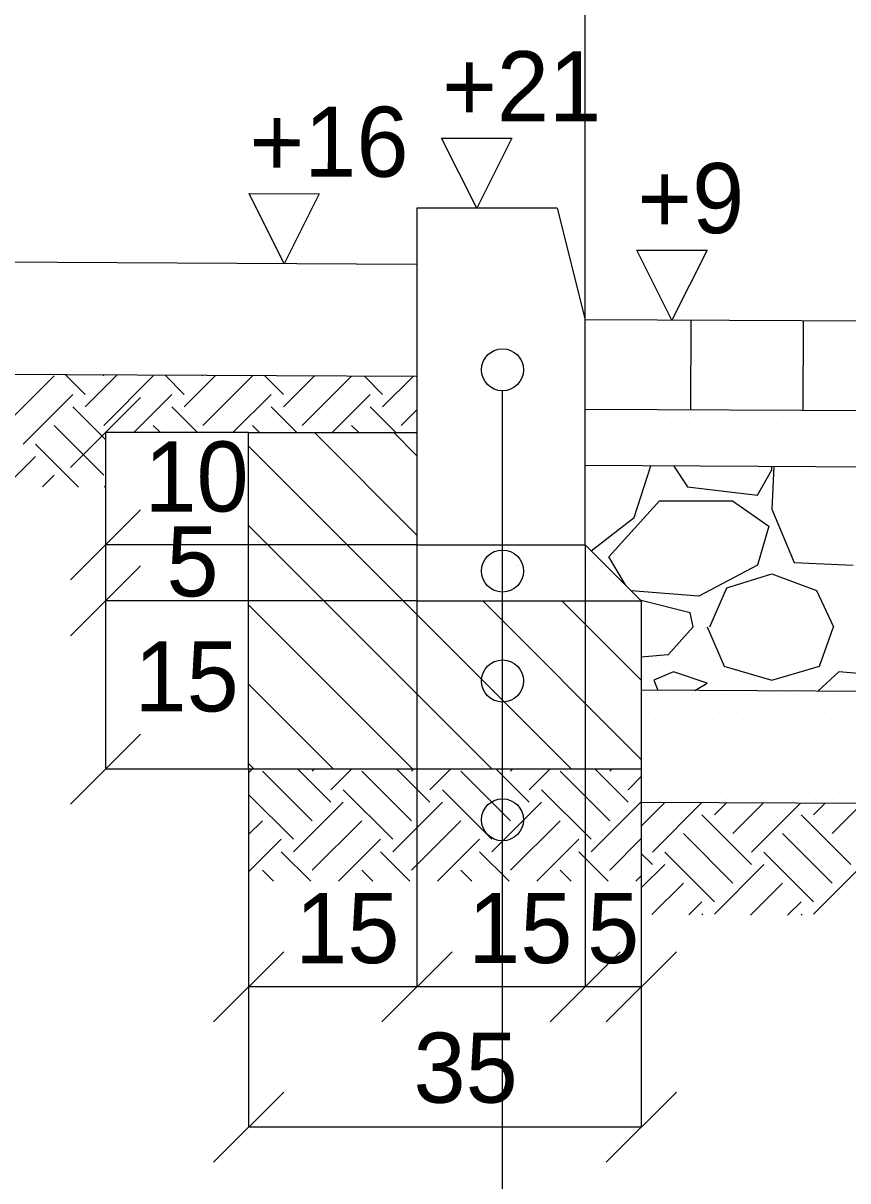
# Model space of a CAD drawing. Extents: x -219625893 to 7498339, y 5791790 to 5792761.
# Drawn here: x 7495188.44 to 7495203.14, y 5791857.84 to 5791878.48 of the extents above; entities that cross this region are included whole.
import ezdxf

# ---------------------------------------------------------------- set-up
doc = ezdxf.new("R2010")
doc.units = 0
for name, color, linetype in [('D_kons_wyp_grunt', 7, 'Continuous'), ('D_kons_wyp_kruszywo_lamane', 7, 'Continuous'), ('D_kons_wyp_podsypka_cem-piask', 7, 'Continuous'), ('D_kons_wyp_pospolka', 7, 'Continuous'), ('D_robocze_1', 7, 'Continuous'), ('D_wymiary_500', 7, 'Continuous'), ('Level 1', 7, 'Continuous'), ('Level 10', 7, 'Continuous'), ('Level 8', 7, 'Continuous'), ('wymiary', 7, 'Continuous')]:
    doc.layers.add(name, color=color, linetype=linetype)

msp = doc.modelspace()

# ---------------------------------------------------------------- linework, layer by layer
at = {"layer": 'D_kons_wyp_grunt'}
for p, q in [((7495188.107, 5791871.309), (7495188.991, 5791872.193)), ((7495189.543, 5791871.862), (7495189.191, 5791872.213)), ((7495189.543, 5791871.641), (7495190.111, 5791872.209)), ((7495189.875, 5791872.193), (7495189.858, 5791872.21)), ((7495189.875, 5791871.309), (7495190.758, 5791872.193)), ((7495191.311, 5791871.862), (7495190.968, 5791872.204)), ((7495191.311, 5791871.641), (7495191.87, 5791872.2)), ((7495191.642, 5791872.193), (7495191.634, 5791872.201)), ((7495191.642, 5791871.309), (7495192.526, 5791872.193)), ((7495193.079, 5791871.862), (7495192.745, 5791872.196)), ((7495193.079, 5791871.641), (7495193.629, 5791872.191)), ((7495193.41, 5791871.309), (7495194.289, 5791872.188)), ((7495194.846, 5791871.862), (7495194.521, 5791872.187)), ((7495194.846, 5791871.641), (7495195.388, 5791872.182)), ((7495188.438, 5791870.978), (7495189.322, 5791871.862)), ((7495190.41, 5791871.182), (7495191.09, 5791871.862)), ((7495192.178, 5791871.182), (7495192.858, 5791871.862)), ((7495193.946, 5791871.182), (7495194.625, 5791871.862)), ((7495189.906, 5791871.057), (7495189.322, 5791871.641)), ((7495191.549, 5791871.182), (7495191.09, 5791871.641)), ((7495193.316, 5791871.182), (7495192.858, 5791871.641)), ((7495195.084, 5791871.182), (7495194.625, 5791871.641)), ((7495195.178, 5791871.309), (7495195.458, 5791871.59)), ((7495189.875, 5791870.425), (7495188.991, 5791871.309)), ((7495190.886, 5791871.182), (7495190.758, 5791871.309)), ((7495192.653, 5791871.182), (7495192.526, 5791871.309)), ((7495194.421, 5791871.182), (7495194.294, 5791871.309)), ((7495189.425, 5791870.212), (7495188.659, 5791870.978)), ((7495188.121, 5791870.219), (7495188.659, 5791870.757)), ((7495188.781, 5791870.215), (7495188.991, 5791870.425)), ((7495189.88, 5791870.21), (7495189.906, 5791870.235)), ((7495192.458, 5791865.118), (7495192.523, 5791865.182)), ((7495193.922, 5791864.593), (7495193.333, 5791865.182)), ((7495193.591, 5791865.145), (7495193.627, 5791865.182)), ((7495193.922, 5791864.814), (7495194.29, 5791865.182)), ((7495195.69, 5791864.593), (7495195.101, 5791865.182)), ((7495195.359, 5791865.145), (7495195.395, 5791865.182)), ((7495195.69, 5791864.814), (7495196.058, 5791865.182)), ((7495197.458, 5791864.593), (7495196.869, 5791865.182)), ((7495197.126, 5791865.145), (7495197.163, 5791865.182)), ((7495197.458, 5791864.814), (7495197.826, 5791865.182)), ((7495199.226, 5791864.593), (7495198.637, 5791865.182)), ((7495198.894, 5791865.145), (7495198.931, 5791865.182)), ((7495193.591, 5791864.262), (7495192.707, 5791865.145)), ((7495195.359, 5791864.262), (7495194.475, 5791865.145)), ((7495197.126, 5791864.262), (7495196.242, 5791865.145)), ((7495198.894, 5791864.262), (7495198.01, 5791865.145)), ((7495199.226, 5791864.814), (7495199.458, 5791865.047)), ((7495195.027, 5791863.93), (7495194.143, 5791864.814)), ((7495196.795, 5791863.93), (7495195.911, 5791864.814)), ((7495198.563, 5791863.93), (7495197.679, 5791864.814)), ((7495193.259, 5791863.93), (7495192.458, 5791864.731)), ((7495193.259, 5791863.709), (7495194.143, 5791864.593)), ((7495195.027, 5791863.709), (7495195.911, 5791864.593)), ((7495196.795, 5791863.709), (7495197.679, 5791864.593)), ((7495198.563, 5791863.709), (7495199.447, 5791864.593)), ((7495199.458, 5791864.167), (7495199.878, 5791864.587)), ((7495199.655, 5791863.701), (7495200.538, 5791864.584)), ((7495200.76, 5791864.364), (7495200.978, 5791864.582)), ((7495201.092, 5791864.033), (7495201.637, 5791864.578)), ((7495201.423, 5791863.701), (7495202.297, 5791864.575)), ((7495202.528, 5791864.364), (7495202.737, 5791864.573)), ((7495202.859, 5791864.033), (7495203.396, 5791864.57)), ((7495201.423, 5791863.48), (7495200.539, 5791864.364)), ((7495203.191, 5791863.48), (7495202.307, 5791864.364)), ((7495192.458, 5791864.013), (7495192.707, 5791864.262)), ((7495193.591, 5791863.378), (7495194.475, 5791864.262)), ((7495195.359, 5791863.378), (7495196.242, 5791864.262)), ((7495197.126, 5791863.378), (7495198.01, 5791864.262)), ((7495192.458, 5791863.35), (7495193.038, 5791863.93)), ((7495194.058, 5791863.182), (7495194.806, 5791863.93)), ((7495195.826, 5791863.182), (7495196.574, 5791863.93)), ((7495197.594, 5791863.182), (7495198.342, 5791863.93)), ((7495198.894, 5791863.378), (7495199.458, 5791863.942)), ((7495201.092, 5791863.149), (7495200.208, 5791864.033)), ((7495202.859, 5791863.149), (7495201.976, 5791864.033)), ((7495193.566, 5791863.182), (7495193.038, 5791863.709)), ((7495195.333, 5791863.182), (7495194.806, 5791863.709)), ((7495197.101, 5791863.182), (7495196.574, 5791863.709)), ((7495198.869, 5791863.182), (7495198.342, 5791863.709)), ((7495199.655, 5791863.48), (7495199.458, 5791863.678)), ((7495200.76, 5791862.817), (7495199.876, 5791863.701)), ((7495202.528, 5791862.817), (7495201.644, 5791863.701)), ((7495192.903, 5791863.182), (7495192.707, 5791863.378)), ((7495194.67, 5791863.182), (7495194.475, 5791863.378)), ((7495196.438, 5791863.182), (7495196.242, 5791863.378)), ((7495198.206, 5791863.182), (7495198.01, 5791863.378)), ((7495199.458, 5791863.062), (7495199.876, 5791863.48)), ((7495200.76, 5791862.596), (7495201.644, 5791863.48)), ((7495202.528, 5791862.596), (7495203.412, 5791863.48)), ((7495199.361, 5791863.182), (7495199.458, 5791863.279)), ((7495199.647, 5791862.588), (7495200.208, 5791863.149)), ((7495201.406, 5791862.58), (7495201.976, 5791863.149)), ((7495200.307, 5791862.585), (7495200.539, 5791862.817)), ((7495202.066, 5791862.576), (7495202.307, 5791862.817)), ((7495200.552, 5791862.584), (7495200.539, 5791862.596)), ((7495202.328, 5791862.575), (7495202.307, 5791862.596))]:
    msp.add_line(p, q, dxfattribs=at)
at = {"layer": 'D_kons_wyp_kruszywo_lamane'}
msp.add_line((7495198.582, 5791869.072), (7495198.567, 5791869.074), dxfattribs=at)
at = {"layer": 'D_kons_wyp_podsypka_cem-piask'}
for p, q in [((7495198.74, 5791871.343), (7495198.74, 5791871.343)), ((7495199.052, 5791871.343), (7495199.052, 5791871.343)), ((7495199.365, 5791871.343), (7495199.365, 5791871.343)), ((7495199.677, 5791871.343), (7495199.677, 5791871.343)), ((7495199.99, 5791871.343), (7495199.99, 5791871.343)), ((7495200.302, 5791871.343), (7495200.302, 5791871.343)), ((7495200.615, 5791871.343), (7495200.615, 5791871.343)), ((7495200.927, 5791871.343), (7495200.927, 5791871.343)), ((7495201.24, 5791871.343), (7495201.24, 5791871.343)), ((7495201.552, 5791871.343), (7495201.552, 5791871.343)), ((7495201.865, 5791871.343), (7495201.865, 5791871.343)), ((7495202.177, 5791871.343), (7495202.177, 5791871.343)), ((7495202.49, 5791871.343), (7495202.49, 5791871.343)), ((7495202.802, 5791871.343), (7495202.802, 5791871.343)), ((7495203.115, 5791871.343), (7495203.115, 5791871.343)), ((7495198.583, 5791871.031), (7495198.583, 5791871.031)), ((7495198.896, 5791871.031), (7495198.896, 5791871.031)), ((7495199.208, 5791871.031), (7495199.208, 5791871.031)), ((7495199.521, 5791871.031), (7495199.521, 5791871.031)), ((7495199.833, 5791871.031), (7495199.833, 5791871.031)), ((7495200.146, 5791871.031), (7495200.146, 5791871.031)), ((7495200.458, 5791871.031), (7495200.458, 5791871.031)), ((7495200.771, 5791871.031), (7495200.771, 5791871.031)), ((7495201.083, 5791871.031), (7495201.083, 5791871.031)), ((7495201.396, 5791871.031), (7495201.396, 5791871.031)), ((7495201.708, 5791871.031), (7495201.708, 5791871.031)), ((7495202.021, 5791871.031), (7495202.021, 5791871.031)), ((7495202.333, 5791871.031), (7495202.333, 5791871.031)), ((7495202.646, 5791871.031), (7495202.646, 5791871.031)), ((7495202.958, 5791871.031), (7495202.958, 5791871.031)), ((7495198.74, 5791870.718), (7495198.74, 5791870.718)), ((7495199.052, 5791870.718), (7495199.052, 5791870.718)), ((7495199.365, 5791870.718), (7495199.365, 5791870.718)), ((7495199.677, 5791870.718), (7495199.677, 5791870.718)), ((7495199.99, 5791870.718), (7495199.99, 5791870.718)), ((7495200.302, 5791870.718), (7495200.302, 5791870.718)), ((7495200.615, 5791870.718), (7495200.615, 5791870.718)), ((7495200.927, 5791870.718), (7495200.927, 5791870.718)), ((7495201.24, 5791870.718), (7495201.24, 5791870.718)), ((7495201.552, 5791870.718), (7495201.552, 5791870.718)), ((7495201.865, 5791870.718), (7495201.865, 5791870.718)), ((7495202.177, 5791870.718), (7495202.177, 5791870.718)), ((7495202.49, 5791870.718), (7495202.49, 5791870.718)), ((7495202.802, 5791870.718), (7495202.802, 5791870.718)), ((7495203.115, 5791870.718), (7495203.115, 5791870.718)), ((7495195.532, 5791869.128), (7495195.532, 5791869.128)), ((7495195.844, 5791869.128), (7495195.844, 5791869.128)), ((7495196.157, 5791869.128), (7495196.157, 5791869.128)), ((7495196.469, 5791869.128), (7495196.469, 5791869.128)), ((7495196.782, 5791869.128), (7495196.782, 5791869.128)), ((7495197.094, 5791869.128), (7495197.094, 5791869.128)), ((7495197.407, 5791869.128), (7495197.407, 5791869.128)), ((7495197.719, 5791869.128), (7495197.719, 5791869.128)), ((7495198.032, 5791869.128), (7495198.032, 5791869.128)), ((7495198.344, 5791869.128), (7495198.344, 5791869.128)), ((7495195.688, 5791868.815), (7495195.688, 5791868.815)), ((7495196, 5791868.815), (7495196, 5791868.815)), ((7495196.313, 5791868.815), (7495196.313, 5791868.815)), ((7495196.625, 5791868.815), (7495196.625, 5791868.815)), ((7495196.938, 5791868.815), (7495196.938, 5791868.815)), ((7495197.25, 5791868.815), (7495197.25, 5791868.815)), ((7495197.563, 5791868.815), (7495197.563, 5791868.815)), ((7495197.875, 5791868.815), (7495197.875, 5791868.815)), ((7495198.188, 5791868.815), (7495198.188, 5791868.815)), ((7495198.5, 5791868.815), (7495198.5, 5791868.815)), ((7495198.813, 5791868.815), (7495198.813, 5791868.815)), ((7495195.532, 5791868.503), (7495195.532, 5791868.503)), ((7495195.844, 5791868.503), (7495195.844, 5791868.503)), ((7495196.157, 5791868.503), (7495196.157, 5791868.503)), ((7495196.469, 5791868.503), (7495196.469, 5791868.503)), ((7495196.782, 5791868.503), (7495196.782, 5791868.503)), ((7495197.094, 5791868.503), (7495197.094, 5791868.503)), ((7495197.407, 5791868.503), (7495197.407, 5791868.503)), ((7495197.719, 5791868.503), (7495197.719, 5791868.503)), ((7495198.032, 5791868.503), (7495198.032, 5791868.503)), ((7495198.344, 5791868.503), (7495198.344, 5791868.503)), ((7495198.657, 5791868.503), (7495198.657, 5791868.503)), ((7495198.969, 5791868.503), (7495198.969, 5791868.503)), ((7495195.688, 5791868.19), (7495195.688, 5791868.19)), ((7495196, 5791868.19), (7495196, 5791868.19)), ((7495196.313, 5791868.19), (7495196.313, 5791868.19)), ((7495196.625, 5791868.19), (7495196.625, 5791868.19)), ((7495196.938, 5791868.19), (7495196.938, 5791868.19)), ((7495197.25, 5791868.19), (7495197.25, 5791868.19)), ((7495197.563, 5791868.19), (7495197.563, 5791868.19)), ((7495197.875, 5791868.19), (7495197.875, 5791868.19)), ((7495198.188, 5791868.19), (7495198.188, 5791868.19)), ((7495198.5, 5791868.19), (7495198.5, 5791868.19)), ((7495198.813, 5791868.19), (7495198.813, 5791868.19)), ((7495199.125, 5791868.19), (7495199.125, 5791868.19)), ((7495199.438, 5791868.19), (7495199.438, 5791868.19))]:
    msp.add_line(p, q, dxfattribs=at)
at = {"layer": 'D_kons_wyp_pospolka'}
for p, q in [((7495199.332, 5791869.667), (7495199.627, 5791870.589)), ((7495200.036, 5791870.587), (7495200.282, 5791870.216)), ((7495201.782, 5791870.517), (7495201.782, 5791870.578)), ((7495201.819, 5791870.578), (7495201.782, 5791869.816)), ((7495201.532, 5791870.066), (7495201.782, 5791870.516)), ((7495200.282, 5791870.217), (7495201.532, 5791870.067)), ((7495198.882, 5791868.966), (7495199.782, 5791869.966)), ((7495199.782, 5791869.967), (7495201.082, 5791869.967)), ((7495201.082, 5791869.966), (7495201.732, 5791869.516)), ((7495201.783, 5791869.816), (7495202.183, 5791868.866)), ((7495198.566, 5791869.074), (7495199.332, 5791869.667)), ((7495201.732, 5791869.517), (7495201.532, 5791868.817)), ((7495199.174, 5791868.466), (7495198.882, 5791868.967)), ((7495201.532, 5791868.816), (7495200.482, 5791868.266)), ((7495202.182, 5791868.867), (7495203.232, 5791868.817)), ((7495200.982, 5791868.417), (7495201.782, 5791868.667)), ((7495201.782, 5791868.667), (7495202.582, 5791868.367)), ((7495200.482, 5791868.266), (7495199.277, 5791868.363)), ((7495200.682, 5791867.717), (7495200.982, 5791868.417)), ((7495202.582, 5791868.367), (7495202.882, 5791867.717)), ((7495200.332, 5791867.966), (7495199.454, 5791868.186)), ((7495200.382, 5791867.717), (7495200.332, 5791867.967)), ((7495200.382, 5791867.716), (7495199.932, 5791867.216)), ((7495200.633, 5791867.716), (7495200.933, 5791867.016)), ((7495202.632, 5791867.016), (7495202.882, 5791867.716)), ((7495199.932, 5791867.217), (7495199.458, 5791867.175)), ((7495200.932, 5791867.017), (7495201.782, 5791866.767)), ((7495201.782, 5791866.767), (7495202.632, 5791867.017)), ((7495200.032, 5791866.916), (7495199.682, 5791866.766)), ((7495200.632, 5791866.716), (7495200.032, 5791866.916)), ((7495202.982, 5791866.917), (7495202.607, 5791866.574)), ((7495204.182, 5791866.817), (7495202.982, 5791866.917)), ((7495199.682, 5791866.767), (7495199.754, 5791866.588)), ((7495200.413, 5791866.585), (7495200.632, 5791866.717)), ((7495199.75, 5791866.508), (7495199.75, 5791866.508)), ((7495200.063, 5791866.508), (7495200.063, 5791866.508)), ((7495200.375, 5791866.508), (7495200.375, 5791866.508)), ((7495200.688, 5791866.508), (7495200.688, 5791866.508)), ((7495201, 5791866.508), (7495201, 5791866.508)), ((7495201.313, 5791866.508), (7495201.313, 5791866.508)), ((7495201.625, 5791866.508), (7495201.625, 5791866.508)), ((7495201.938, 5791866.508), (7495201.938, 5791866.508)), ((7495202.25, 5791866.508), (7495202.25, 5791866.508)), ((7495202.563, 5791866.508), (7495202.563, 5791866.508)), ((7495202.875, 5791866.508), (7495202.875, 5791866.508)), ((7495199.594, 5791866.195), (7495199.594, 5791866.195)), ((7495199.906, 5791866.195), (7495199.906, 5791866.195)), ((7495200.219, 5791866.195), (7495200.219, 5791866.195)), ((7495200.531, 5791866.195), (7495200.531, 5791866.195)), ((7495200.844, 5791866.195), (7495200.844, 5791866.195)), ((7495201.156, 5791866.195), (7495201.156, 5791866.195)), ((7495201.469, 5791866.195), (7495201.469, 5791866.195)), ((7495201.781, 5791866.195), (7495201.781, 5791866.195)), ((7495202.094, 5791866.195), (7495202.094, 5791866.195)), ((7495202.406, 5791866.195), (7495202.406, 5791866.195)), ((7495202.719, 5791866.195), (7495202.719, 5791866.195)), ((7495203.031, 5791866.195), (7495203.031, 5791866.195)), ((7495199.75, 5791865.883), (7495199.75, 5791865.883)), ((7495200.063, 5791865.883), (7495200.063, 5791865.883)), ((7495200.375, 5791865.883), (7495200.375, 5791865.883)), ((7495200.688, 5791865.883), (7495200.688, 5791865.883)), ((7495201, 5791865.883), (7495201, 5791865.883)), ((7495201.313, 5791865.883), (7495201.313, 5791865.883)), ((7495201.625, 5791865.883), (7495201.625, 5791865.883)), ((7495201.938, 5791865.883), (7495201.938, 5791865.883)), ((7495202.25, 5791865.883), (7495202.25, 5791865.883)), ((7495202.563, 5791865.883), (7495202.563, 5791865.883)), ((7495202.875, 5791865.883), (7495202.875, 5791865.883)), ((7495199.594, 5791865.57), (7495199.594, 5791865.57)), ((7495199.906, 5791865.57), (7495199.906, 5791865.57)), ((7495200.219, 5791865.57), (7495200.219, 5791865.57)), ((7495200.531, 5791865.57), (7495200.531, 5791865.57)), ((7495200.844, 5791865.57), (7495200.844, 5791865.57)), ((7495201.156, 5791865.57), (7495201.156, 5791865.57)), ((7495201.469, 5791865.57), (7495201.469, 5791865.57)), ((7495201.781, 5791865.57), (7495201.781, 5791865.57)), ((7495202.094, 5791865.57), (7495202.094, 5791865.57)), ((7495202.406, 5791865.57), (7495202.406, 5791865.57)), ((7495202.719, 5791865.57), (7495202.719, 5791865.57)), ((7495203.031, 5791865.57), (7495203.031, 5791865.57)), ((7495199.75, 5791865.258), (7495199.75, 5791865.258)), ((7495200.063, 5791865.258), (7495200.063, 5791865.258)), ((7495200.375, 5791865.258), (7495200.375, 5791865.258)), ((7495200.688, 5791865.258), (7495200.688, 5791865.258)), ((7495201, 5791865.258), (7495201, 5791865.258)), ((7495201.313, 5791865.258), (7495201.313, 5791865.258)), ((7495201.625, 5791865.258), (7495201.625, 5791865.258)), ((7495201.938, 5791865.258), (7495201.938, 5791865.258)), ((7495202.25, 5791865.258), (7495202.25, 5791865.258)), ((7495202.563, 5791865.258), (7495202.563, 5791865.258)), ((7495202.875, 5791865.258), (7495202.875, 5791865.258)), ((7495199.594, 5791864.945), (7495199.594, 5791864.945)), ((7495199.906, 5791864.945), (7495199.906, 5791864.945)), ((7495200.219, 5791864.945), (7495200.219, 5791864.945)), ((7495200.531, 5791864.945), (7495200.531, 5791864.945)), ((7495200.844, 5791864.945), (7495200.844, 5791864.945)), ((7495201.156, 5791864.945), (7495201.156, 5791864.945)), ((7495201.469, 5791864.945), (7495201.469, 5791864.945)), ((7495201.781, 5791864.945), (7495201.781, 5791864.945)), ((7495202.094, 5791864.945), (7495202.094, 5791864.945)), ((7495202.406, 5791864.945), (7495202.406, 5791864.945)), ((7495202.719, 5791864.945), (7495202.719, 5791864.945)), ((7495203.031, 5791864.945), (7495203.031, 5791864.945)), ((7495199.75, 5791864.633), (7495199.75, 5791864.633)), ((7495200.063, 5791864.633), (7495200.063, 5791864.633)), ((7495200.375, 5791864.633), (7495200.375, 5791864.633)), ((7495200.688, 5791864.633), (7495200.688, 5791864.633)), ((7495201, 5791864.633), (7495201, 5791864.633)), ((7495201.313, 5791864.633), (7495201.313, 5791864.633)), ((7495201.625, 5791864.633), (7495201.625, 5791864.633)), ((7495201.938, 5791864.633), (7495201.938, 5791864.633)), ((7495202.25, 5791864.633), (7495202.25, 5791864.633)), ((7495202.563, 5791864.633), (7495202.563, 5791864.633)), ((7495202.875, 5791864.633), (7495202.875, 5791864.633))]:
    msp.add_line(p, q, dxfattribs=at)
at = {"layer": 'D_robocze_1'}
for p, q in [((7495195.458, 5791869.354), (7495193.63, 5791871.182)), ((7495195.458, 5791870.768), (7495195.044, 5791871.182)), ((7495198.216, 5791865.182), (7495192.458, 5791870.939)), ((7495196.801, 5791865.182), (7495192.458, 5791869.525)), ((7495195.387, 5791865.182), (7495192.458, 5791868.111)), ((7495199.458, 5791865.354), (7495196.63, 5791868.182)), ((7495199.458, 5791866.768), (7495198.044, 5791868.182)), ((7495193.973, 5791865.182), (7495192.458, 5791866.697)), ((7495192.559, 5791865.182), (7495192.458, 5791865.283))]:
    msp.add_line(p, q, dxfattribs=at)
at = {"layer": 'D_wymiary_500'}
for p, q in [((7495198.458, 5791873.194), (7495198.458, 5791895.3)), ((7495195.442, 5791872.182), (7495183.88, 5791872.24)), ((7495192.458, 5791871.182), (7495189.906, 5791871.182)), ((7495189.906, 5791871.182), (7495189.906, 5791865.182)), ((7495195.458, 5791869.182), (7495189.906, 5791869.182)), ((7495198.458, 5791869.182), (7495198.458, 5791861.298)), ((7495195.458, 5791868.182), (7495189.906, 5791868.182)), ((7495195.458, 5791868.182), (7495195.458, 5791861.298)), ((7495192.458, 5791865.182), (7495189.906, 5791865.182)), ((7495192.458, 5791865.182), (7495192.458, 5791858.798)), ((7495199.458, 5791865.182), (7495199.458, 5791858.798)), ((7495199.458, 5791861.298), (7495192.458, 5791861.298)), ((7495199.458, 5791858.798), (7495192.458, 5791858.798))]:
    msp.add_line(p, q, dxfattribs=at)
at = {"layer": 'Level 1'}
for p, q in [((7495196.523, 5791875.182), (7495195.899, 5791876.432)), ((7495195.899, 5791876.432), (7495197.149, 5791876.432)), ((7495197.149, 5791876.432), (7495196.523, 5791875.182)), ((7495193.09, 5791874.194), (7495192.466, 5791875.444)), ((7495192.466, 5791875.444), (7495193.716, 5791875.443)), ((7495193.716, 5791875.443), (7495193.09, 5791874.194)), ((7495200.004, 5791873.187), (7495199.38, 5791874.437)), ((7495199.38, 5791874.437), (7495200.63, 5791874.436)), ((7495200.63, 5791874.436), (7495200.004, 5791873.187))]:
    msp.add_line(p, q, dxfattribs=at)
at = {"layer": 'Level 10'}
for p, q in [((7495197.961, 5791875.182), (7495198.458, 5791873.194)), ((7495195.452, 5791874.182), (7495183.88, 5791874.24)), ((7495246.391, 5791872.955), (7495198.458, 5791873.194)), ((7495200.341, 5791871.585), (7495200.349, 5791873.185)), ((7495202.342, 5791871.575), (7495202.35, 5791873.175)), ((7495246.391, 5791871.355), (7495198.45, 5791871.594)), ((7495193.094, 5791865.182), (7495193.094, 5791865.182)), ((7495197.337, 5791865.182), (7495197.337, 5791865.182))]:
    msp.add_line(p, q, dxfattribs=at)
at = {"layer": 'Level 8'}
for p, q in [((7495197.961, 5791875.182), (7495195.458, 5791875.182)), ((7495195.458, 5791875.182), (7495195.458, 5791869.182)), ((7495198.458, 5791869.182), (7495198.458, 5791873.194)), ((7495192.458, 5791865.182), (7495192.458, 5791871.182)), ((7495192.458, 5791871.182), (7495195.458, 5791871.182)), ((7495195.458, 5791869.182), (7495198.458, 5791869.182)), ((7495198.458, 5791869.182), (7495199.458, 5791868.182)), ((7495199.458, 5791868.182), (7495199.458, 5791865.182)), ((7495199.458, 5791865.182), (7495192.458, 5791865.182))]:
    msp.add_line(p, q, dxfattribs=at)
msp.add_lwpolyline([(7495195.458, 5791869.182), (7495195.458, 5791868.182), (7495199.458, 5791868.182)], dxfattribs=at)
at = {"layer": 'wymiary'}
for p, q in [((7495189.28, 5791870.558), (7495190.531, 5791871.807)), ((7495196.983, 5791845.421), (7495196.983, 5791871.927)), ((7495246.386, 5791870.355), (7495198.445, 5791870.594)), ((7495189.28, 5791868.558), (7495190.531, 5791869.807)), ((7495189.28, 5791867.558), (7495190.531, 5791868.807)), ((7495246.366, 5791866.355), (7495199.458, 5791866.589)), ((7495189.28, 5791864.558), (7495190.531, 5791865.807)), ((7495246.356, 5791864.355), (7495199.458, 5791864.589)), ((7495191.833, 5791860.674), (7495193.084, 5791861.923)), ((7495194.833, 5791860.674), (7495196.084, 5791861.923)), ((7495197.833, 5791860.674), (7495199.084, 5791861.923)), ((7495198.833, 5791860.674), (7495200.084, 5791861.923)), ((7495191.833, 5791858.174), (7495193.084, 5791859.423)), ((7495198.833, 5791858.174), (7495200.084, 5791859.423))]:
    msp.add_line(p, q, dxfattribs=at)
for centre in [(7495196.983, 5791872.303), (7495196.983, 5791868.714), (7495196.983, 5791866.753), (7495196.983, 5791864.278)]:
    msp.add_circle(centre, 0.375, dxfattribs=at)

# ---------------------------------------------------------------- texts
at = {"layer": 'D_wymiary_500'}
for s, p in [('10', (7495190.599, 5791869.774)), ('5', (7495190.993, 5791868.262)), ('15', (7495190.423, 5791866.209)), ('15', (7495193.288, 5791861.72)), ('15', (7495196.371, 5791861.722)), ('5', (7495198.492, 5791861.722)), ('35', (7495195.397, 5791859.232))]:
    msp.add_text(s, height=1.25, rotation=0.0429, dxfattribs=at).set_placement(p)
at = {"layer": 'wymiary'}
for s, p in [('+21', (7495195.906, 5791876.735)), ('+16', (7495192.473, 5791875.747)), ('+9', (7495199.387, 5791874.74))]:
    msp.add_text(s, height=1.25, rotation=359.9571, dxfattribs=at).set_placement(p)

doc.saveas('drawing.dxf')
